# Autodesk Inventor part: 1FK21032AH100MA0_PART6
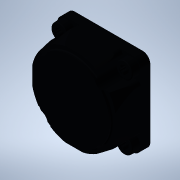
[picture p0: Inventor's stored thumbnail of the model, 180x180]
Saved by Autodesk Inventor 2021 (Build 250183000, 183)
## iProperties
Created: 2025-04
Part Number: 1FK21032AH100MA0_PART6
Material: Generic
Catalog Web Link: www.3dfindit.com
Description: -Servo synchronous motor
Document SubType Name: Modeling
Designer: psAdmin
Mass: 3.85693 g
Surface Area: 17.8404 cm^2
Volume: 3.85693 cm^3
Density: 1 g/cm^3
Appearance: PSOLRGB-48-56-69
Category: PARTsolutions
Title: 1FK21032AH100MA0_PART6
Author: Cadenas PARTsolutions
Comments: Servo synchronous motor
Sending System: PARTsolutions
Preprocessor: ST-DEVELOPER v19.3
PSOL_IDENT_0: {$CADENAS_DATA/23d-libs/siemens_ag/_cat_/12/33/1fk21032ah100ma0.prj},213 {VTYP=3D},{NB=1FK21032AH100
PSOL_IDENT_1: MA0_PART6},{LINA=1FK21032AH100MA0_PART6},{NN=1FK21032AH100MA0_PART6},{NOPRJ=TRUE},{DATE=19.08.2025 1
PSOL_IDENT_2: 4:00:27},{GEOMDATE=30.07.2025 02:02:58},{VERSION=},{LINEID=10},{WBVAR=},{WBNUMERIC=}  {NB=1FK21032AH
PSOL_IDENT_3: 100MA0_PART6},{LINA=1FK21032AH100MA0_PART6},{KT=DUMMY},{PREVIEW=../../../_pool_/d3/78/p_d211_xx_0093
PSOL_IDENT_4: 4j.png},{DESCSHORT=SIMOTICS S-1FK2 HD, SINAMICS S210 3AC 400V-480V, 0.59 Nm, 4500 rpm},{DESCLONG=SIM
PSOL_IDENT_5: OTICS S-1FK2 HD servo motor M0=0.64 Nm; PN = 0.28 kW at nN=4500 rpm (380-480 V); PN = 0.167 kW at nN=
PSOL_IDENT_6: 2500 rpm (200-240 V); with holding brake; degree of protection IP64; cylindrical shaft D14 x 30 mm;
PSOL_IDENT_7: absolute encoder 22-bit + 12-bit multiturn (encoder AM22DQC); with OCC interface; plug size M17, rot
PSOL_IDENT_8: atable; SIMOTICS S-1FK2 servomotorfor a wide range of uses in industrial environments. SIMOTICS S‑1F
PSOL_IDENT_9: K2 servomotors are compact synchronous motors with a high dynamic performance that set themselves ap
PSOL_IDENT_10: art as a result of their high power density, degree of protection and overload capability. The motor
PSOL_IDENT_11: s are available in two variants: as High Dynamic variant (highest dynamic performance as a result of
PSOL_IDENT_12: the low intrinsic moment of inertia for applications demanding a high dynamic performance with low
PSOL_IDENT_13: moved masses) - and as Compact variant (precise and stable closed-loop control for medium up to larg
PSOL_IDENT_14: e moved masses as a result of a medium intrinsic moment of inertia). SIMOTICSS‑1FK2 servomotors full
PSOL_IDENT_15: y exploit their strengths in a system with the SINAMICSS210 frequency converter and simple connectio
PSOL_IDENT_16: n using the one cable connection (OCC). Advantages include the short control and positioning times,
PSOL_IDENT_17: fast and precise correction of disturbing quantities as well as stable control with a high dynamic p
PSOL_IDENT_18: erformance. The servo motors can be configured to address a wide range of requirements. For example
PSOL_IDENT_19: with and without holding brake, IP64 or IP65 degree of protection, singleturn or multiturn absolute
PSOL_IDENT_20: encoders - to name just a few. Further, the servomotors are available in different shaft heights ext
PSOL_IDENT_21: ending from 20 to 100. A shaft sealing ring is available to achieve an IP65 degree of protection and
PSOL_IDENT_22: for subsequent mounting at the motor or as spare part. SIMOTICS - the optimum motor for each and ev
PSOL_IDENT_23: ery motion control application.},{INTNO=195125315563},{SUPPLIERALTNO=1FK2103-2AH10-0MA0},{MANUID=1FK
PSOL_IDENT_24: 21032AH100MA0},{MANUNAME=Siemens},{MANUTYPEDESC=SYNCHRONOUS MOTOR 1FK2 HD 0,64 NM},{AAU732=SIMOTICS}
PSOL_IDENT_25: ,{AAO057=S-1FK2},{AAU734=SIMOTICS S-1FK2 HD servo motor M0=0.64 Nm; PN = 0.28 kW at nN=4500 rpm (380
PSOL_IDENT_26: -480 V); PN = 0.167 kW at nN=2500 rpm (200-240 V); with holding brake; degree of protection IP64; cy
PSOL_IDENT_27: lindrical shaft D14 x 30 mm; absolute encoder 22-bit + 12-bit multiturn (encoder AM22DQC); with OCC
PSOL_IDENT_28: interface; plug size M17, rotatable;},{AAW338=SYNCHRONOUS MOTOR 1FK2 HD 0,64 NM},{AAO742=SIMOTICS},{
PSOL_IDENT_29: AAO663=4034106444723},{NOCUPEROU=1},{PRICEQUANTITY=1},{QUANTITYMIN=1},{QUANTITYINT=1},{CTN=85015100}
PSOL_IDENT_30: ,{COO=RO},{AAO676=1FK2103-2AH10-0MA0},{AAO677=Siemens AG},{ORDERUNIT=C62},{CONTENTUNIT=C62}
NB: 1FK21032AH100MA0_PART6
NT: Servo synchronous motor
NBSYN: $MANUID._PART6
LINA: 1FK21032AH100MA0_PART6
CATALOG: SIEMENS
PREVIEW: ../../../_pool_/d3/78/p_d211_xx_00934j.png
DESCSHORT: SIMOTICS S-1FK2 HD, SINAMICS S210 3AC 400V-480V, 0.59 Nm, 4500 rpm
DESCLONG: SIMOTICS S-1FK2 HD servo motor M0=0.64 Nm; PN = 0.28 kW at nN=4500 rpm (380-480 V); PN = 0.167 kW at nN=2500 rpm (200-240 V); with holding brake; degree of prot
INTNO: 195125315563
SUPPLIERALTNO: 1FK2103-2AH10-0MA0
MANUID: 1FK21032AH100MA0
MANUNAME: Siemens
MANUTYPEDESC: SYNCHRONOUS MOTOR 1FK2 HD 0,64 NM
AAU732: SIMOTICS
AAO057: S-1FK2
AAU734: SIMOTICS S-1FK2 HD servo motor M0=0.64 Nm; PN = 0.28 kW at nN=4500 rpm (380-480 V); PN = 0.167 kW at nN=2500 rpm (200-240 V); with holding brake; degree of prot
AAW338: SYNCHRONOUS MOTOR 1FK2 HD 0,64 NM
AAO742: SIMOTICS
AAO663: 4034106444723.0
NOCUPEROU: 1
PRICEQUANTITY: 1
QUANTITYMIN: 1
QUANTITYINT: 1
CTN: 85015100
COO: RO
ARTICLENO: 1FK21032AH100MA0_PART6
BOMINFO: 1FK21032AH100MA0_PART6
CREATOR: CADENAS GmbH
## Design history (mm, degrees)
feature "2025_04_17_15_06_16_0643"
body "Solid1"
